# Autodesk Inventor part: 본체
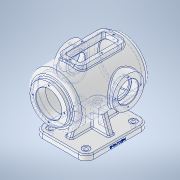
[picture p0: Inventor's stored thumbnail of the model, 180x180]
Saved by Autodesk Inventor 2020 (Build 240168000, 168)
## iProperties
Created: 2021-11
Part Number: 본체
Material: 알루미늄 6061
Document SubType Name: Modeling
Designer: USER
Density: 2.7 g/cm^3
Appearance: 알루미늄 - 평지
Mass: 3544.77 g
Surface Area: 2409.17 cm^2
Volume: 1312.88 cm^3
Author: USER
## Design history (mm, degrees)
sketch "스케치1"
  geometry: L1 (-80, 65)-(80, 65); L2 (80, 65)-(80, -65); L3 (80, -65)-(-80, -65); L4 (-80, -65)-(-80, 65); L5 (-80, 65)-(80, -65); L6 (80, 65)-(-80, -65); 1 further point
  constraints: 12 end point, 2 midpoint, 2 parallel, 1 horizontal, 1 perpendicular
  dimensions: "d0" = 160 distance of L1.start L1.end; "d1" = 130 distance of L3.end L1.start
extrude "돌출1" new body sketch "스케치1" distance "d2" = 14; taper "d3" = 0 deg
fillet "모깎기1" dims "d4" = 20
sketch "스케치3"
  geometry: L1 (60, 65)-(-60, 65) reference; L2 (-80, 45)-(-80, -45) reference; L3 (-60, -65)-(60, -65) reference; L4 (80, -45)-(80, 45) reference; A1 r 20 centre (60, 45) between (80, 45) and (60, 65) reference; A2 r 20 centre (-60, 45) between (-60, 65) and (-80, 45) reference; A3 r 20 centre (-60, -45) between (-80, -45) and (-60, -65) reference; A4 r 20 centre (60, -45) between (60, -65) and (80, -45) reference; 5 further points
  constraints: 4 coincident
hole "구멍2" sketch "스케치3" at (-60, 45), (60, 45), (60, -45), (-60, -45) diameter "d12" = 9; stored, may be unused: countersink angle "d16" = 90 deg, drill point angle "d18" = 118 deg; dims "d13" = 14, "d14" = 18, "d15" = 2, "d17" = 8
fillet "모깎기2" dims "d19" = 3
sketch "스케치5"
  geometry: L1 (-77, 14)-(77, 14) reference; L2 (80, 11)-(80, 0) reference; L3 (80, 0)-(-80, 0) reference; L4 (-80, 0)-(-80, 11) reference; L5 (110, 114)-(-100, 114); L6 (110, 114)-(110, 161.5); L7 (110, 161.5)-(100, 161.5); L8 (100, 161.5)-(100, 179); L9 (100, 179)-(-75.993, 179); A1 r 3 centre (-77, 11) between (-77, 14) and (-80, 11) reference; A2 r 3 centre (77, 11) between (80, 11) and (77, 14) reference; A3 r 100 centre (0, 114) between (-75.993, 179) and (-100, 114); 1 further point
  constraints: 10 end point, 3 perpendicular, 2 point on circle, 1 centre point, 1 horizontal, 1 point on line, 1 vertical
  dimensions: "d27" = 210 distance of L5.start L5.end; "d28" = 114 distance from line of L3.end L5; "d29" = 100 radius of A3; "d30" = 95 diameter of L7 L5; "d31" = 130 diameter of L9 L5; "d32" = 10 distance of L6.end L7.end; "d33" = 30 horizontal distance of L2.end L5.start
revolve "회전1" sketch "스케치5" stored, may be unused: angle "d34" = 90 deg
fillet "모깎기3" dims "d35" = 10
fillet "모깎기4" dims "d36" = 3
sketch "스케치6"
  geometry: C1 r 47.5 at (0, 0) reference; 2 further points
  constraints: 1 horizontal alignment
  dimensions: "d37" = 40 distance of C1.centre point (40, 0)
hole "구멍3" sketch "스케치6" at (40, 0) diameter "d38" = 3.242; stored, may be unused: countersink angle "d42" = 90 deg, drill point angle "d44" = 118 deg; dims "d39" = 10, "d40" = 18, "d41" = 2, "d43" = 13
sketch "스케치7"
  geometry: L1 (-77, 14)-(77, 14) reference; L2 (80, 11)-(80, 0) reference; L3 (80, 0)-(-80, 0) reference; L4 (-80, 0)-(-80, 11) reference; L5 (103, 161.5)-(110, 161.5) reference; L6 (110, 161.5)-(110, 155.621) reference; L7 (110, 155.621)-(97, 155.621) reference; L8 (97, 155.621)-(96.026, 154) reference; L9 (96.026, 154)-(97, 152.379) reference; L10 (97, 152.379)-(110, 152.379) reference; L11 (110, 152.379)-(110, 75.621) reference; L12 (110, 75.621)-(97, 75.621) reference; L13 (97, 75.621)-(96.026, 74) reference; L14 (96.026, 74)-(97, 72.379) reference; L15 (97, 72.379)-(110, 72.379) reference; L16 (110, 72.379)-(110, 66.5) reference; L17 (110, 66.5)-(103, 66.5) reference; L18 (100, 63.5)-(100, 59) reference; L19 (90, 49)-(-75.993, 49) reference; L20 (-75.993, 179)-(90, 179) reference; L21 (100, 169)-(100, 164.5) reference; L22 (-100, 114)-(110, 114); L23 (110, 146.5)-(85, 146.5); L24 (85, 146.5)-(85, 169); L25 (85, 169)-(-71.239, 169); A1 r 3 centre (-77, 11) between (-77, 14) and (-80, 11) reference; A2 r 3 centre (77, 11) between (80, 11) and (77, 14) reference; A3 r 3 centre (103, 164.5) between (100, 164.5) and (103, 161.5) reference; A4 r 3 centre (103, 63.5) between (103, 66.5) and (100, 63.5) reference; A5 r 10 centre (90, 59) between (90, 49) and (100, 59) reference; A6 r 100 centre (0, 114) between (-75.993, 179) and (-75.993, 49) reference; A7 r 10 centre (90, 169) between (100, 169) and (90, 179) reference; A8 r 100 centre (0, 114) between (-75.993, 179) and (-75.993, 49) reference; A9 r 90 centre (0, 114) between (-71.239, 169) and (-90, 114); 1 further point
  constraints: 8 end point, 4 point on circle, 2 perpendicular, 2 point on line, 1 centre point, 1 horizontal, 1 midpoint
  dimensions: "d48" = 10 radial gap between concentric circles of A8 A9; "d49" = 110 diameter of L25 L22; "d50" = 65 diameter of L23 L22; "d51" = 25 distance of L23.start L23.end
revolve "회전2" sketch "스케치7" stored, may be unused: angle "d52" = 90 deg
fillet "모깎기5" dims "d53" = 3
chamfer "모따기1" distance "d54" = 1; stored, may be unused: second distance "d55" = 2, angle "d56" = 45 deg
node "작업 평면1"
sketch "스케치8"
  geometry: L1 (-60, 30)-(60, 30); L2 (60, 30)-(60, -30); L3 (60, -30)-(-60, -30); L4 (-60, -30)-(-60, 30); L5 (-60, 30)-(60, -30); L6 (60, 30)-(-60, -30); L7 (-110, 47.5)-(-110, -47.5) reference; 3 further points
  constraints: 12 end point, 3 midpoint, 2 parallel, 1 horizontal, 1 horizontal alignment, 1 perpendicular
  dimensions: "d58" = 120 distance of L1.start L1.end; "d59" = 60 distance of L3.end L1.start; "d60" = 50 distance between parallel lines of L7 L4
extrude "돌출2" join sketch "스케치8" stored distance "d61" = 10; taper "d62" = 0 deg
fillet "모깎기6" dims "d63" = 15
sketch "스케치9"
  geometry: L1 (-50, 20)-(50, 20); L2 (50, 20)-(50, -20); L3 (50, -20)-(-50, -20); L4 (-50, -20)-(-50, 20); L5 (-50, 20)-(50, -20); L6 (50, 20)-(-50, -20); L7 (45, 30)-(-45, 30) reference; L8 (-60, 15)-(-60, -15) reference; 1 further point
  constraints: 12 end point, 2 midpoint, 2 parallel, 1 horizontal, 1 perpendicular
  dimensions: "d64" = 10 distance between parallel lines of L1 L7; "d65" = 10 distance between parallel lines of L8 L4
extrude "돌출3" cut sketch "스케치9" stored distance "d66" = 10; taper "d67" = 0 deg
fillet "모깎기7" dims "d68" = 5
fillet "모깎기8" dims "d69" = 3
sketch "스케치10"
  geometry: 5 further points
  constraints: 2 horizontal alignment, 2 vertical alignment
  dimensions: "d70" = 50 distance of point (0, -25) point (0, 25); "d71" = 25 distance of point (0, 0) point (0, 25); "d72" = 55 distance of point (0, 0) point (-55, 0); "d73" = 55 distance of point (0, 0) point (55, 0)
hole "구멍4" sketch "스케치10" at (0, 25), (0, -25), (55, 0), (-55, 0) diameter "d74" = 3.242; stored, may be unused: countersink angle "d78" = 90 deg, drill point angle "d80" = 118 deg; dims "d75" = 9, "d76" = 4, "d77" = 2, "d79" = 11
node "작업 평면2"
sketch "스케치11"
  geometry: L1 (-75.993, 179)-(90, 179) reference; L2 (90, 49)-(90, 179) reference; L3 (45, 184)-(-45, 184) reference; L4 (-60, 180.325)-(-60, 184) reference; C1 r 40 at (-17, 114); 2 further points
  constraints: 1 centre point, 1 horizontal alignment, 1 midpoint
  dimensions: "d82" = 80 diameter of C1; "d83" = 43 distance from line of C1.centre L4
extrude "돌출4" join sketch "스케치11" stored distance "d84" = 10; taper "d85" = 0 deg
sketch "스케치12"
  geometry: C1 r 40 at (0, 0) reference; 2 further points
  constraints: 1 vertical alignment
  dimensions: "d86" = 32.5 distance of point (0, 32.5) C1.centre
hole "구멍5" sketch "스케치12" at (0, 32.5) diameter "d87" = 3.242; stored, may be unused: countersink angle "d91" = 90 deg, drill point angle "d93" = 118 deg; dims "d88" = 11, "d89" = 4, "d90" = 2, "d92" = 13
fillet "모깎기9" dims "d97" = 3
sketch "스케치13"
  geometry: C1 r 26 at (0, 0); C2 r 40 at (0, 0) reference; 1 further point
  constraints: 1 centre point, 1 coincident
  dimensions: "d98" = 52 diameter of C1
extrude "돌출5" cut sketch "스케치13" distance "d99" = 18; taper "d100" = 0 deg
sketch "스케치14"
  geometry: C1 r 40 at (0, 0) reference; C2 r 21 at (0, 0); 1 further point
  constraints: 1 centre point, 1 coincident
  dimensions: "d101" = 42 diameter of C2
extrude "돌출6" cut sketch "스케치14" stored distance "d102" = 18; taper "d103" = 0 deg
chamfer "모따기2" distance "d104" = 1; stored, may be unused: second distance "d105" = 2, angle "d106" = 45 deg
fillet "모깎기10" dims "d107" = 3
sketch "스케치15"
  geometry: C1 r 40 at (0, 0) reference; C2 r 26 at (0, 0); 1 further point
  constraints: 1 centre point, 1 coincident
  dimensions: "d108" = 52 diameter of C2
extrude "돌출7" cut sketch "스케치15" distance "d109" = 18; taper "d110" = 0 deg
chamfer "모따기3" distance "d111" = 1; stored, may be unused: second distance "d112" = 2, angle "d113" = 45 deg
sketch "스케치16"
  geometry: C1 r 40 at (0, 0) reference; C2 r 21 at (0, 0); 1 further point
  constraints: 1 centre point, 1 coincident
  dimensions: "d114" = 42 diameter of C2
extrude "돌출8" cut sketch "스케치16" extent not by distance; stored distance "d115" = 18; taper "d116" = 0 deg
sketch "스케치17"
  geometry: L1 (53.6, 101.671)-(57, 101.671) reference; L2 (57, 101.671)-(57, 94.328) reference; L3 (57, 94.328)-(74, 94.328) reference; L4 (75, 93.024)-(75, 77.792) reference; L5 (75, 77.792)-(55.758, 77.792) reference; L6 (-55.758, 77.792)-(-75, 77.792) reference; L7 (-75, 77.792)-(-75, 93.024) reference; L8 (-74, 94.328)-(-57, 94.328) reference; L9 (-57, 94.328)-(-57, 101.671) reference; L10 (25, 172.026)-(26.621, 173) reference; L11 (26.621, 173)-(26.621, 184) reference; L12 (26.621, 184)-(30, 184) reference; L13 (30, 184)-(30, 173.456) reference; L14 (55.758, 150.208)-(75, 150.208) reference; L15 (75, 150.208)-(75, 134.976) reference; L16 (74, 133.672)-(57, 133.672) reference; L17 (57, 133.672)-(57, 126.329) reference; L18 (57, 126.329)-(53.6, 126.329) reference; L19 (20, 165.235)-(20, 184) reference; L20 (20, 184)-(23.379, 184) reference; L21 (23.379, 184)-(23.379, 173) reference; L22 (23.379, 173)-(25, 172.026) reference; L23 (-25, 172.026)-(-23.379, 173) reference; L24 (-23.379, 173)-(-23.379, 184) reference; L25 (-23.379, 184)-(-20, 184) reference; L26 (-20, 184)-(-20, 165.235) reference; L27 (-57, 126.329)-(-57, 133.672) reference; L28 (-57, 133.672)-(-74, 133.672) reference; L29 (-75, 134.976)-(-75, 150.208) reference; L30 (-75, 150.208)-(-55.758, 150.208) reference; L31 (-30, 173.456)-(-30, 184) reference; L32 (-30, 184)-(-26.621, 184) reference; L33 (-26.621, 184)-(-26.621, 173) reference; L34 (-26.621, 173)-(-25, 172.026) reference; L35 (-62, 14)-(62, 14) reference; L36 (65, 11)-(65, 0) reference; L37 (65, 0)-(-65, 0) reference; L38 (-65, 0)-(-65, 11) reference; L39 (-33.809, 58.485)-(-50, 14); L40 (33.809, 58.485)-(50, 14); L41 (-57, 101.671)-(-53.6, 101.671) reference; L42 (-53.6, 126.329)-(-57, 126.329) reference; A1 r 55 centre (0, 114) between (-53.6, 101.671) and (53.6, 101.671) reference; A2 r 65 centre (0, 114) between (-52.911, 76.246) and (52.911, 76.246) reference; A3 r 3 centre (33, 173.456) between (30, 173.456) and (31.544, 170.833) reference; A4 r 65 centre (0, 114) between (52.911, 151.754) and (31.544, 170.833) reference; A5 r 55 centre (0, 114) between (53.6, 126.329) and (20, 165.235) reference; A6 r 55 centre (0, 114) between (-20, 165.235) and (-53.6, 126.329) reference; A7 r 65 centre (0, 114) between (-31.544, 170.833) and (-52.911, 151.754) reference; A8 r 3 centre (-33, 173.456) between (-31.544, 170.833) and (-30, 173.456) reference; A9 r 3 centre (62, 11) between (65, 11) and (62, 14) reference; A10 r 3 centre (-62, 11) between (-62, 14) and (-65, 11) reference; 4 further points
  constraints: 4 end point, 2 point on line, 11 other
  dimensions: "d117" = 110 deg angle of L35 L40; "d118" = 110 deg angle of L35 L39; "d119" = 100 distance of L40.end L39.end; "d120" = 50 horizontal distance of point (0, 0) L40.end
extrude "돌출9" join sketch "스케치17" stored distance "d121" = 14; taper "d122" = 0 deg
sketch "스케치18"
  geometry: L1 (100, 63.5)-(100, 59) reference; L2 (90, 49)-(7, 49) reference; L3 (7, 49)-(7, 14) reference; L4 (7, 14)-(77, 14) reference; L5 (80, 11)-(80, 0) reference; L6 (80, 0)-(-80, 0) reference; L7 (-80, 0)-(-80, 11) reference; L8 (-77, 14)-(-7, 14) reference; L9 (-7, 14)-(-7, 49) reference; L10 (-7, 49)-(-75.993, 49) reference; L11 (-75.993, 179)-(-63, 179) reference; L12 (-60, 182)-(-60, 184) reference; L13 (-60, 184)-(-56.621, 184) reference; L14 (-56.621, 184)-(-56.621, 173) reference; L15 (-56.621, 173)-(-55, 172.026) reference; L16 (-55, 172.026)-(-53.379, 173) reference; L17 (-53.379, 173)-(-53.379, 184) reference; L18 (-53.379, 184)-(-50, 184) reference; L19 (-50, 184)-(-50, 169) reference; L20 (-50, 169)-(-69.75, 169) reference; L21 (-69.75, 59)-(82, 59) reference; L22 (85, 62)-(85, 81.5) reference; L23 (85, 81.5)-(109, 81.5) reference; L24 (109, 81.5)-(110, 80.5) reference; L25 (110, 80.5)-(110, 75.621) reference; L26 (110, 75.621)-(97, 75.621) reference; L27 (97, 75.621)-(96.026, 74) reference; L28 (96.026, 74)-(97, 72.379) reference; L29 (97, 72.379)-(110, 72.379) reference; L30 (110, 72.379)-(110, 66.5) reference; L31 (110, 66.5)-(103, 66.5) reference; L32 (103, 161.5)-(110, 161.5) reference; L33 (110, 161.5)-(110, 155.621) reference; L34 (110, 155.621)-(97, 155.621) reference; L35 (97, 155.621)-(96.026, 154) reference; L36 (96.026, 154)-(97, 152.379) reference; L37 (97, 152.379)-(110, 152.379) reference; L38 (110, 152.379)-(110, 147.5) reference; L39 (110, 147.5)-(109, 146.5) reference; L40 (109, 146.5)-(85, 146.5) reference; L41 (85, 146.5)-(85, 166) reference; L42 (82, 169)-(50, 169) reference; L43 (50, 169)-(50, 184) reference; L44 (50, 184)-(53.379, 184) reference; L45 (53.379, 184)-(53.379, 173) reference; L46 (53.379, 173)-(55, 172.026) reference; L47 (55, 172.026)-(56.621, 173) reference; L48 (56.621, 173)-(56.621, 184) reference; L49 (56.621, 184)-(60, 184) reference; L50 (60, 184)-(60, 182) reference; L51 (63, 179)-(90, 179) reference; L52 (100, 169)-(100, 164.5) reference; L53 (-75.993, 49)-(90, 49) reference; L54 (47.261, 49)-(60, 14); A1 r 3 centre (103, 63.5) between (103, 66.5) and (100, 63.5) reference; A2 r 10 centre (90, 59) between (90, 49) and (100, 59) reference; A3 r 3 centre (77, 11) between (80, 11) and (77, 14) reference; A4 r 3 centre (-77, 11) between (-77, 14) and (-80, 11) reference; A5 r 100 centre (0, 114) between (-75.993, 179) and (-75.993, 49) reference; A6 r 3 centre (-63, 182) between (-63, 179) and (-60, 182) reference; A7 r 3 centre (-69.75, 166) between (-69.75, 169) and (-72.155, 167.793) reference; A8 r 90 centre (0, 114) between (-72.155, 167.793) and (-72.155, 60.207) reference; A9 r 3 centre (-69.75, 62) between (-72.155, 60.207) and (-69.75, 59) reference; A10 r 3 centre (82, 62) between (82, 59) and (85, 62) reference; A11 r 3 centre (103, 164.5) between (100, 164.5) and (103, 161.5) reference; A12 r 3 centre (82, 166) between (85, 166) and (82, 169) reference; A13 r 3 centre (63, 182) between (60, 182) and (63, 179) reference; A14 r 10 centre (90, 169) between (100, 169) and (90, 179) reference; 1 further point
  constraints: 2 end point, 2 point on line
  dimensions: "d123" = 110 deg angle of L4 L54; "d124" = 60 horizontal distance of point (0, 0) L54.end
feature "리브1" sketch "스케치18" dims "d125" = 1, "d126" = 14, "d127" = 0, "d128" = 0, "d129" = 1, "d130" = 1
sketch "스케치19"
  geometry: L1 (100, 63.5)-(100, 59) reference; L2 (90, 49)-(47.261, 49) reference; L3 (47.261, 49)-(60, 14) reference; L4 (60, 14)-(77, 14) reference; L5 (80, 11)-(80, 0) reference; L6 (80, 0)-(-80, 0) reference; L7 (-80, 0)-(-80, 11) reference; L8 (-77, 14)-(-7, 14) reference; L9 (-7, 14)-(-7, 49) reference; L10 (-7, 49)-(-75.993, 49) reference; L11 (-75.993, 179)-(-63, 179) reference; L12 (-60, 182)-(-60, 184) reference; L13 (-60, 184)-(-56.621, 184) reference; L14 (-56.621, 184)-(-56.621, 173) reference; L15 (-56.621, 173)-(-55, 172.026) reference; L16 (-55, 172.026)-(-53.379, 173) reference; L17 (-53.379, 173)-(-53.379, 184) reference; L18 (-53.379, 184)-(-50, 184) reference; L19 (-50, 184)-(-50, 169) reference; L20 (-50, 169)-(-69.75, 169) reference; L21 (-69.75, 59)-(82, 59) reference; L22 (85, 62)-(85, 81.5) reference; L23 (85, 81.5)-(109, 81.5) reference; L24 (109, 81.5)-(110, 80.5) reference; L25 (110, 80.5)-(110, 75.621) reference; L26 (110, 75.621)-(97, 75.621) reference; L27 (97, 75.621)-(96.026, 74) reference; L28 (96.026, 74)-(97, 72.379) reference; L29 (97, 72.379)-(110, 72.379) reference; L30 (110, 72.379)-(110, 66.5) reference; L31 (110, 66.5)-(103, 66.5) reference; L32 (103, 161.5)-(110, 161.5) reference; L33 (110, 161.5)-(110, 155.621) reference; L34 (110, 155.621)-(97, 155.621) reference; L35 (97, 155.621)-(96.026, 154) reference; L36 (96.026, 154)-(97, 152.379) reference; L37 (97, 152.379)-(110, 152.379) reference; L38 (110, 152.379)-(110, 147.5) reference; L39 (110, 147.5)-(109, 146.5) reference; L40 (109, 146.5)-(85, 146.5) reference; L41 (85, 146.5)-(85, 166) reference; L42 (82, 169)-(50, 169) reference; L43 (50, 169)-(50, 184) reference; L44 (50, 184)-(53.379, 184) reference; L45 (53.379, 184)-(53.379, 173) reference; L46 (53.379, 173)-(55, 172.026) reference; L47 (55, 172.026)-(56.621, 173) reference; L48 (56.621, 173)-(56.621, 184) reference; L49 (56.621, 184)-(60, 184) reference; L50 (60, 184)-(60, 182) reference; L51 (63, 179)-(90, 179) reference; L52 (100, 169)-(100, 164.5) reference; L53 (-75.993, 49)-(90, 49) reference; L54 (-47.261, 49)-(-60, 14); A1 r 3 centre (103, 63.5) between (103, 66.5) and (100, 63.5) reference; A2 r 10 centre (90, 59) between (90, 49) and (100, 59) reference; A3 r 3 centre (77, 11) between (80, 11) and (77, 14) reference; A4 r 3 centre (-77, 11) between (-77, 14) and (-80, 11) reference; A5 r 100 centre (0, 114) between (-75.993, 179) and (-75.993, 49) reference; A6 r 3 centre (-63, 182) between (-63, 179) and (-60, 182) reference; A7 r 3 centre (-69.75, 166) between (-69.75, 169) and (-72.155, 167.793) reference; A8 r 90 centre (0, 114) between (-72.155, 167.793) and (-72.155, 60.207) reference; A9 r 3 centre (-69.75, 62) between (-72.155, 60.207) and (-69.75, 59) reference; A10 r 3 centre (82, 62) between (82, 59) and (85, 62) reference; A11 r 3 centre (103, 164.5) between (100, 164.5) and (103, 161.5) reference; A12 r 3 centre (82, 166) between (85, 166) and (82, 169) reference; A13 r 3 centre (63, 182) between (60, 182) and (63, 179) reference; A14 r 10 centre (90, 169) between (100, 169) and (90, 179) reference; 1 further point
  constraints: 2 end point, 2 point on line
  dimensions: "d131" = 110 deg angle of L8 L54; "d132" = 60 horizontal distance of point (0, 0) L54.end
feature "리브2" sketch "스케치19" dims "d133" = 1, "d134" = 14, "d135" = 0, "d136" = 0, "d137" = 1, "d138" = 1
fillet "모깎기11" dims "d139" = 3
fillet "모깎기12" dims "d140" = 3
fillet "모깎기13" dims "d141" = 3
node "작업 평면3"
sketch "스케치20"
  geometry: 2 further points
  constraints: 1 vertical alignment, 1 other
  dimensions: "d143" = 5 distance of point (60, 0) point (60, 5)
feature "엠보싱1" sketch "스케치20" dims "d144" = 0.5, "d145" = 0
fillet "모깎기14" dims "d146" = 0.3
fillet "모깎기15" dims "d147" = 3
fillet "모깎기16" dims "d148" = 10
node "솔리드1"
pattern_circular "원형 패턴1" dims angle "d46" = 360 deg
pattern_circular "원형 패턴2" dims angle "d95" = 360 deg
mirror "미러1"
node "투영된 루프1"
node "투영된 루프2"
node "절단 모서리 투영2"
node "절단 모서리 투영3"
node "절단 모서리 투영4"
node "절단 모서리 투영5"
node "절단 모서리 투영6"
feature "A9D066F2-1C7D-4E18-AEED-F7BC21143FA4" dims "d12" = 9, "d13" = 14, "d14" = 18, "d15" = 2, "d16" = 90 deg, "d17" = 8, "d18" = 118 deg
other parameters: "d57" = 184, "d81" = -75, "d142" = 20.25
